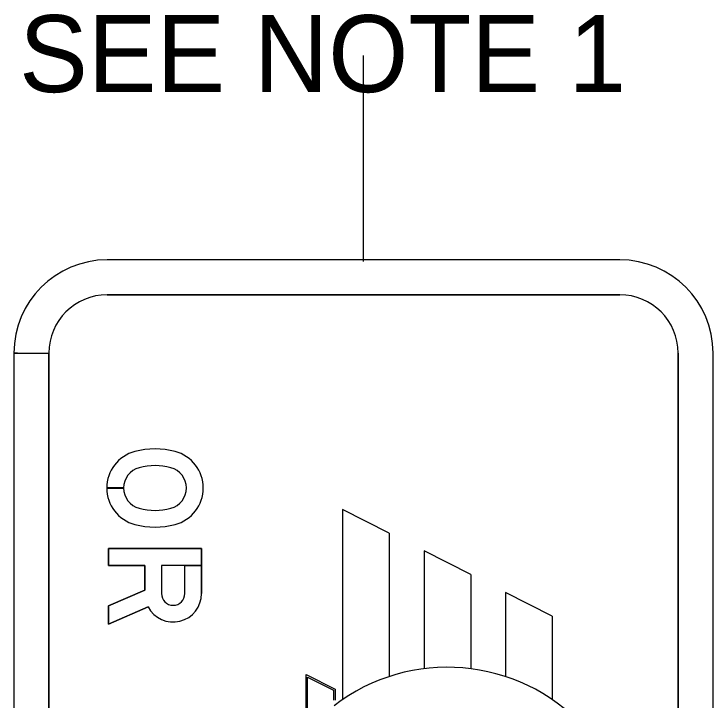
# Model space of a CAD drawing. Extents: x 46672 to 47298, y 5424 to 5742.
# Drawn here: x 46900.23 to 46925.64, y 5716.74 to 5741.69 of the extents above; entities that cross this region are included whole.
import ezdxf

# ---------------------------------------------------------------- set-up
doc = ezdxf.new("R2010")
doc.units = 0
doc.layers.add('SheetBorder_dp', color=7, linetype='Continuous')
doc.layers.add('TextNotes', color=7, linetype='Continuous')

msp = doc.modelspace()

# ---------------------------------------------------------------- linework, layer by layer
at = {"layer": 'TextNotes'}
for p, q in [((46912.938, 5732.686), (46912.938, 5740.186)), ((46922.255, 5732.75), (46903.621, 5732.75)), ((46922.255, 5732.75), (46903.621, 5732.75)), ((46922.255, 5732.75), (46903.621, 5732.75)), ((46922.255, 5731.48), (46903.621, 5731.48)), ((46903.621, 5731.48), (46922.255, 5731.48)), ((46903.621, 5731.48), (46922.255, 5731.48)), ((46900.233, 5729.362), (46900.233, 5675.152)), ((46900.233, 5729.362), (46900.233, 5675.152)), ((46900.233, 5729.362), (46901.503, 5729.362)), ((46900.233, 5729.362), (46901.503, 5729.362)), ((46900.233, 5729.362), (46900.36, 5729.362)), ((46900.36, 5729.361), (46900.233, 5729.361)), ((46900.233, 5729.349), (46900.233, 5675.152)), ((46901.503, 5729.349), (46900.233, 5729.349)), ((46900.233, 5729.349), (46900.233, 5675.152)), ((46901.503, 5729.349), (46900.233, 5729.349)), ((46901.503, 5729.362), (46901.503, 5675.152)), ((46901.503, 5675.152), (46901.503, 5729.349)), ((46901.503, 5675.152), (46901.503, 5729.349)), ((46924.373, 5675.152), (46924.373, 5729.362)), ((46924.373, 5729.362), (46924.373, 5675.152)), ((46924.373, 5729.362), (46924.373, 5675.152)), ((46925.644, 5675.152), (46925.644, 5729.362)), ((46925.644, 5675.152), (46925.644, 5729.362)), ((46925.644, 5675.152), (46925.644, 5729.362)), ((46925.644, 5675.152), (46925.644, 5729.362)), ((46904.215, 5724.453), (46903.605, 5724.453)), ((46904.215, 5724.453), (46903.605, 5724.453)), ((46903.605, 5724.452), (46904.215, 5724.452)), ((46903.605, 5724.452), (46904.215, 5724.452)), ((46912.178, 5723.674), (46912.178, 5716.758)), ((46913.872, 5722.812), (46912.178, 5723.674)), ((46913.872, 5722.812), (46913.872, 5717.592)), ((46915.143, 5722.166), (46915.143, 5717.88)), ((46916.836, 5721.303), (46915.143, 5722.166)), ((46916.836, 5721.303), (46916.836, 5717.88)), ((46918.106, 5720.657), (46918.106, 5717.592)), ((46919.8, 5719.795), (46918.106, 5720.657)), ((46919.8, 5719.795), (46919.8, 5716.758)), ((46910.853, 5717.668), (46911.906, 5717.131)), ((46910.853, 5716.436), (46910.853, 5717.668)), ((46910.908, 5717.577), (46911.851, 5717.097)), ((46910.908, 5709.11), (46910.908, 5717.577)), ((46911.851, 5717.097), (46911.851, 5716.742)), ((46911.906, 5717.131), (46911.906, 5716.742))]:
    msp.add_line(p, q, dxfattribs=at)
for points in [[(46907.053, 5720.612), (46907.053, 5722.25), (46903.665, 5722.25), (46903.665, 5721.64), (46904.986, 5721.64), (46904.986, 5720.743), (46903.665, 5720.17), (46903.665, 5719.506), (46905.106, 5720.13)], [(46905.106, 5720.13), (46903.665, 5719.506), (46903.665, 5720.17), (46904.986, 5720.743), (46904.986, 5721.64), (46903.665, 5721.64), (46903.665, 5722.25), (46907.053, 5722.25), (46907.053, 5721.641), (46905.596, 5721.64), (46905.596, 5720.612)], [(46905.106, 5720.13), (46903.665, 5719.506), (46903.665, 5720.17), (46904.986, 5720.743), (46904.986, 5721.64), (46903.665, 5721.64), (46903.665, 5722.25), (46907.053, 5722.25), (46907.053, 5721.641), (46905.596, 5721.64), (46905.596, 5720.612)], [(46906.443, 5720.612), (46906.443, 5721.64), (46905.596, 5721.64), (46905.596, 5720.612)], [(46906.443, 5721.64), (46907.053, 5721.64), (46907.053, 5720.612)], [(46906.443, 5720.612), (46906.443, 5721.64)], [(46906.443, 5721.64), (46907.053, 5721.64), (46907.053, 5720.612)], [(46906.443, 5720.612), (46906.443, 5721.64)]]:
    msp.add_lwpolyline(points, dxfattribs=at)
for centre, radius, start, end in [((46903.621, 5729.362), 3.388, 90, 180), ((46903.621, 5729.362), 3.388, 90, 180), ((46903.621, 5729.362), 3.388, 90, 180), ((46922.255, 5729.362), 3.388, 360, 90), ((46922.255, 5729.362), 3.388, 360, 90), ((46922.255, 5729.362), 3.388, 360, 90), ((46903.621, 5729.362), 2.118, 90, 180), ((46903.621, 5729.362), 2.118, 90, 180), ((46903.621, 5729.362), 2.118, 90, 180), ((46922.255, 5729.362), 2.118, 360, 90), ((46922.255, 5729.362), 2.118, 360, 90), ((46922.255, 5729.362), 2.118, 360, 90), ((46905.359, 5723.03), 2.846, 75.0382, 104.9618), ((46905.359, 5723.03), 2.846, 75.0382, 104.9618), ((46905.359, 5723.03), 2.846, 75.0382, 104.9618), ((46904.978, 5724.453), 1.373, 104.9618, 255.0382), ((46904.978, 5724.453), 1.373, 104.9618, 180), ((46904.978, 5724.453), 1.373, 104.9618, 180), ((46905.739, 5724.453), 1.373, 284.9618, 75.0382), ((46905.739, 5724.453), 1.373, 284.9618, 75.0382), ((46905.739, 5724.453), 1.373, 284.9618, 75.0382), ((46904.978, 5724.453), 0.763, 104.9618, 255.0382), ((46904.978, 5724.453), 0.763, 104.9618, 180), ((46904.978, 5724.453), 0.763, 104.9618, 180), ((46905.359, 5723.03), 2.236, 75.0382, 104.9618), ((46905.359, 5723.03), 2.236, 75.0382, 104.9618), ((46905.359, 5723.03), 2.236, 75.0382, 104.9618), ((46905.739, 5724.453), 0.763, 284.9618, 75.0382), ((46905.739, 5724.453), 0.763, 284.9618, 75.0382), ((46905.739, 5724.453), 0.763, 284.9618, 75.0382), ((46904.978, 5724.453), 1.373, 180.0071, 255.0382), ((46904.978, 5724.453), 1.373, 180.0071, 255.0382), ((46904.978, 5724.453), 0.763, 180.0127, 255.0382), ((46904.978, 5724.453), 0.763, 180.0127, 255.0382), ((46905.359, 5725.876), 2.236, 255.0382, 284.9618), ((46905.359, 5725.876), 2.236, 255.0382, 284.9618), ((46905.359, 5725.876), 2.236, 255.0382, 284.9618), ((46905.359, 5725.876), 2.846, 255.0382, 284.9618), ((46905.359, 5725.876), 2.846, 255.0382, 284.9618), ((46905.359, 5725.876), 2.846, 255.0382, 284.9618), ((46906.019, 5720.612), 1.033, 207.837, 360), ((46906.019, 5720.612), 1.033, 207.837, 360), ((46906.019, 5720.612), 1.033, 207.837, 360), ((46906.019, 5720.612), 0.424, 180, 360), ((46906.019, 5720.612), 0.424, 180, 360), ((46906.019, 5720.612), 0.424, 180, 360), ((46915.989, 5711.158), 6.775, 318.5904, 127.4727)]:
    msp.add_arc(centre, radius, start, end, dxfattribs=at)

# ---------------------------------------------------------------- texts
at = {"layer": 'SheetBorder_dp'}
msp.add_text('SEE NOTE 1', height=2.8, dxfattribs=at).set_placement((46900.42, 5738.85))

doc.saveas('drawing.dxf')
